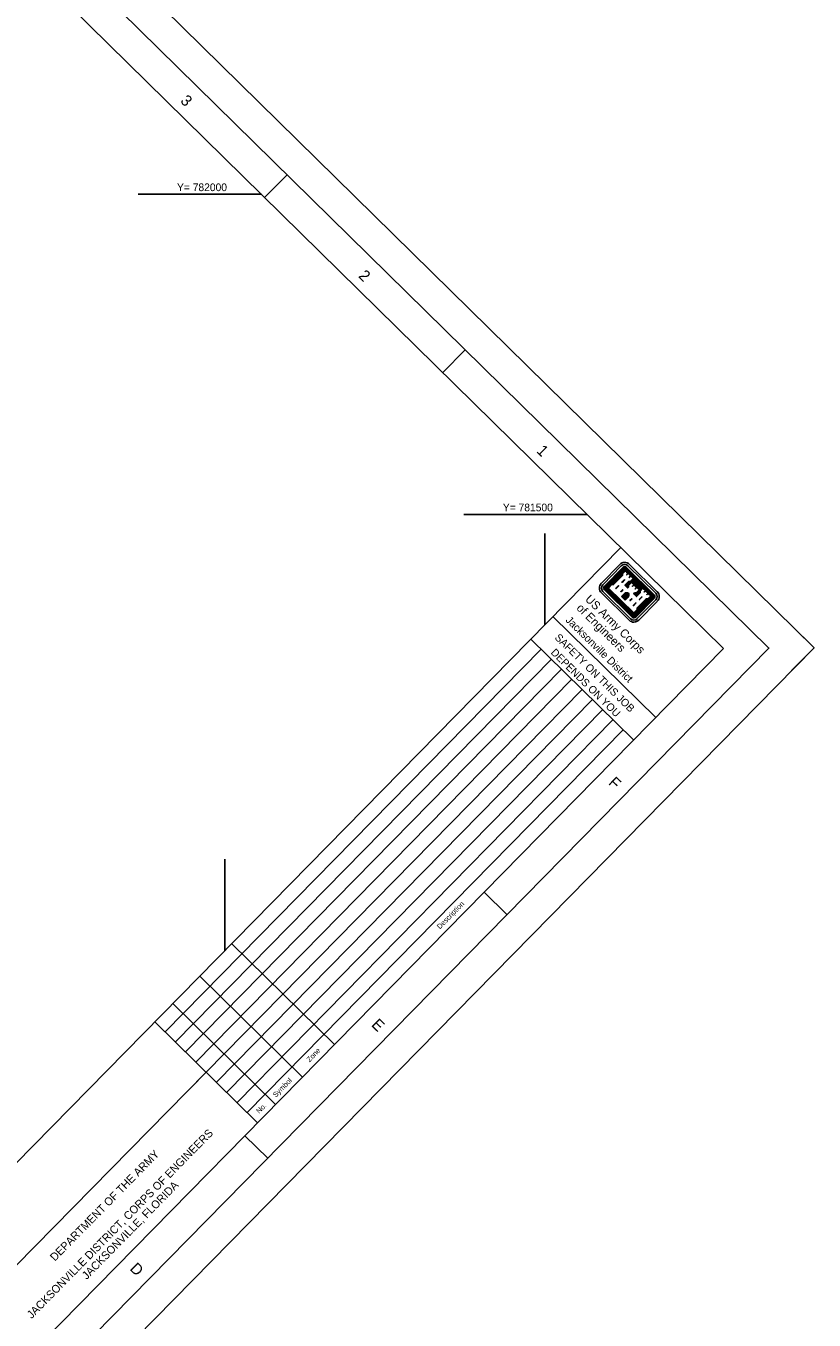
# Model space of a CAD drawing. Extents: x 614899 to 620420, y 778867 to 784376.
# Drawn here: x 619189 to 620420, y 780242 to 782263 of the extents above; entities that cross this region are included whole.
import ezdxf

# ---------------------------------------------------------------- set-up
doc = ezdxf.new("R2010")
doc.units = 0
for name, color, linetype in [('G-ANNO-NPLT', 7, 'Continuous'), ('G-ANNO-TEXT-LOGO', 7, 'Continuous'), ('G-ANNO-TEXT-TTLB', 7, 'Continuous'), ('G-ANNO-TTLB', 7, 'Continuous'), ('V-TOPO-COOR-STAT', 7, 'Continuous')]:
    doc.layers.add(name, color=color, linetype=linetype)

msp = doc.modelspace()

# ---------------------------------------------------------------- linework, layer by layer
at = {"layer": 'G-ANNO-NPLT'}
msp.add_lwpolyline([(617282, 784375.7), (620420.5, 781292), (618037.6, 778866.8), (614899.1, 781950.5)], close=True, dxfattribs=at)
msp.add_lwpolyline([(620385.4, 781256.3), (620420.5, 781292), (620384.8, 781327)], dxfattribs=at)
at = {"layer": 'G-ANNO-TEXT-LOGO'}
for p, q in [((620116.9, 781421.9), (620088.2, 781392.7)), ((620090.4, 781390.4), (620119.2, 781419.7)), ((620121.7, 781417.2), (620092.9, 781388)), ((620122.3, 781416.6), (620093.6, 781387.3)), ((620122.9, 781416), (620094.1, 781386.8)), ((620123.5, 781415.4), (620094.8, 781386.2)), ((620124.2, 781414.8), (620095.4, 781385.5)), ((620124.8, 781414.1), (620096.3, 781385.1)), ((620125.4, 781413.6), (620097.5, 781385.2)), ((620119.8, 781406.9), (620105.1, 781391.9)), ((620119.8, 781405.6), (620106.4, 781392)), ((620168.3, 781372.2), (620124.9, 781414.8)), ((620168.9, 781372.9), (620125.6, 781415.5)), ((620169.5, 781373.4), (620126.1, 781416.1)), ((620170.1, 781374.1), (620126.8, 781416.7)), ((620170.8, 781374.7), (620127.4, 781417.3)), ((620129.8, 781419.8), (620173.1, 781377.2)), ((620175.4, 781379.4), (620132, 781422)), ((620138.2, 781341.6), (620094.8, 781384.2)), ((620138.7, 781342.1), (620095.4, 781384.7)), ((620139.1, 781343.1), (620096.3, 781385.1)), ((620139.1, 781344.3), (620097.5, 781385.2)), ((620135.8, 781395.8), (620149.1, 781382.7)), ((620136.4, 781396.4), (620149.7, 781383.4)), ((620137, 781397), (620150.2, 781384)), ((620137.6, 781397.6), (620150.9, 781384.6)), ((620138.2, 781398.3), (620151.5, 781385.2)), ((620138.8, 781398.8), (620152.1, 781385.8)), ((620139.4, 781399.5), (620152.7, 781386.4)), ((620088.2, 781377.5), (620131.6, 781334.9)), ((620133.9, 781337.2), (620090.5, 781379.8)), ((620136.3, 781339.7), (620093, 781382.3)), ((620136.9, 781340.3), (620093.5, 781382.9)), ((620137.5, 781340.9), (620094.2, 781383.5)), ((620119.6, 781371.7), (620124.3, 781376.5)), ((620119.6, 781371.7), (620125.3, 781366.1)), ((620120.2, 781371.2), (620124.9, 781376)), ((620120.8, 781370.5), (620125.5, 781375.3)), ((620121.4, 781369.9), (620126.1, 781374.7)), ((620122, 781369.3), (620126.7, 781374.1)), ((620122.9, 781368.5), (620127.6, 781373.3)), ((620123.4, 781367.9), (620128.1, 781372.7)), ((620124.1, 781367.3), (620128.8, 781372.1)), ((620124.7, 781366.7), (620129.4, 781371.5)), ((620125.3, 781366.1), (620130, 781370.9)), ((620167, 781372.6), (620139.1, 781344.3)), ((620167.6, 781372.1), (620139.1, 781343.1)), ((620168.2, 781371.5), (620139.5, 781342.2)), ((620168.9, 781370.8), (620140.2, 781341.6)), ((620169.5, 781370.3), (620140.7, 781341)), ((620170.1, 781369.6), (620141.4, 781340.4)), ((620170.7, 781369), (620142, 781339.8)), ((620173.2, 781366.6), (620144.4, 781337.4)), ((620159.2, 781366.9), (620145.8, 781353.3)), ((620160.4, 781366.9), (620145.8, 781352)), ((620146.8, 781335.1), (620175.5, 781364.3))]:
    msp.add_line(p, q, dxfattribs=at)
for points in [[(620125.9, 781413.1), (620120.3, 781407.4), (620120.4, 781405), (620107, 781391.4), (620104.5, 781391.3), (620098.4, 781385.1), (620139.1, 781345.2), (620145.2, 781351.4), (620145.1, 781353.9), (620158.5, 781367.5), (620161, 781367.5), (620166.5, 781373.1), (620161.2, 781378.4), (620157, 781382.5), (620153.2, 781386.2), (620147.7, 781380.6), (620147.8, 781378.1), (620142.9, 781373.1), (620139.9, 781376), (620140.4, 781376.5), (620143, 781376.5), (620148.4, 781382.1), (620143.1, 781387.4), (620138.9, 781391.4), (620135.2, 781395.1), (620129.7, 781389.6), (620129.7, 781387), (620129.2, 781386.5), (620126.2, 781389.5), (620131.1, 781394.5), (620133.6, 781394.4), (620139.1, 781400), (620133.8, 781405.3), (620129.7, 781409.4), (620125.9, 781413.1)], [(620125.8, 781411.9), (620121.2, 781407.2), (620121.2, 781404.6), (620107.3, 781390.5), (620104.8, 781390.5), (620099.6, 781385.2), (620139.1, 781346.4), (620144.3, 781351.7), (620144.2, 781354.3), (620158.1, 781368.4), (620160.7, 781368.3), (620165.3, 781373.1), (620161.5, 781376.8), (620159.3, 781374.6), (620159, 781375), (620161.1, 781377.2), (620157.3, 781380.9), (620155.2, 781378.7), (620154.9, 781379), (620157.1, 781381.2), (620153.2, 781385), (620148.6, 781380.3), (620148.6, 781377.7), (620142.9, 781371.9), (620138.8, 781376), (620140.1, 781377.4), (620142.7, 781377.4), (620147.3, 781382.1), (620143.4, 781385.9), (620141.3, 781383.7), (620141, 781383.9), (620143.2, 781386.2), (620139.3, 781389.9), (620137.1, 781387.7), (620136.8, 781388.1), (620138.9, 781390.3), (620135.2, 781394), (620130.5, 781389.3), (620130.6, 781386.7), (620129.2, 781385.4), (620125.1, 781389.5), (620130.8, 781395.2), (620133.3, 781395.3), (620137.9, 781400), (620134.2, 781403.7), (620132, 781401.5), (620131.6, 781401.8), (620133.8, 781404), (620130, 781407.8), (620127.8, 781405.6), (620127.5, 781405.9), (620129.7, 781408.1), (620125.8, 781411.9)], [(620114.8, 781389), (620110.7, 781384.8), (620111.1, 781384.4), (620115.3, 781388.6), (620114.8, 781389)], [(620124.2, 781398.5), (620120.1, 781394.4), (620120.5, 781393.9), (620124.6, 781398.1), (620124.2, 781398.5)], [(620132.2, 781393.6), (620131.5, 781393.5), (620127.5, 781389.5), (620128.9, 781388.1), (620128.8, 781390), (620132.3, 781393.6)], [(620121.4, 781382.6), (620118.5, 781379.6), (620118.9, 781379.3), (620121.8, 781382.2), (620121.4, 781382.6)], [(620136.1, 781368.1), (620133.2, 781365.2), (620132.9, 781365.6), (620135.7, 781368.5), (620136.1, 781368.1)], [(620146.9, 781379.1), (620146.9, 781378.4), (620142.9, 781374.3), (620141.6, 781375.6), (620143.4, 781375.7), (620146.9, 781379.3)], [(620151.9, 781371.2), (620147.8, 781367.1), (620147.5, 781367.5), (620151.6, 781371.6), (620151.9, 781371.2)], [(620142.6, 781361.8), (620138.5, 781357.5), (620138.1, 781357.9), (620142.2, 781362.1), (620142.6, 781361.8)]]:
    msp.add_lwpolyline(points, dxfattribs=at)
for centre, major_axis, start_param, end_param in [((620124.6, 781414.4), (7.64, -7.51), 1.57078, 3.141576), ((620124.6, 781414.4), (5.34, -5.25), 1.57078, 3.141576), ((620124.6, 781414.4), (2.87, -2.82), 1.57078, 3.141576), ((620124.6, 781414.4), (2.25, -2.21), 1.57078, 3.141576), ((620124.6, 781414.4), (1.63, -1.6), 1.57078, 3.141576), ((620124.6, 781414.4), (1.01, -0.99), 1.57078, 3.141576), ((620124.6, 781414.4), (0.389, -0.382), 1.57078, 3.141576), ((620095.8, 781385.1), (-7.64, 7.51), 6.28317, 7.853966), ((620095.8, 781385.1), (-5.34, 5.25), 6.28317, 7.853966), ((620095.8, 781385.1), (-2.87, 2.82), 6.28317, 7.853966), ((620095.8, 781385.1), (-2.25, 2.21), 6.28317, 7.853966), ((620095.8, 781385.1), (-1.63, 1.6), 6.28317, 7.853966), ((620095.8, 781385.1), (-1.01, 0.99), 6.28317, 7.853966), ((620095.8, 781385.1), (-0.389, 0.382), 6.28317, 7.853966), ((620127.9, 781372.4), (-3.96, 3.89), 4.985832, 6.214359), ((620127.9, 781372.4), (-3.34, 3.28), 4.947465, 6.21436), ((620127.9, 781372.4), (-2.72, 2.68), 4.947465, 6.21436), ((620127.9, 781372.4), (-2.1, 2.07), 4.947465, 6.21436), ((620127.9, 781372.4), (-1.48, 1.46), 4.947465, 6.214359), ((620125.7, 781374.5), (1.48, -1.46), 0.068794, 1.335689), ((620125.7, 781374.5), (2.1, -2.07), 0.068794, 1.335689), ((620125.7, 781374.5), (2.72, -2.68), 0.068795, 1.335689), ((620125.7, 781374.5), (3.34, -3.28), 0.068795, 1.335689), ((620125.7, 781374.5), (3.96, -3.89), 0.068795, 1.29842), ((620167.9, 781371.9), (0.389, -0.382), 6.283169, 7.853965), ((620167.9, 781371.9), (1.01, -0.99), 6.283169, 7.853965), ((620167.9, 781371.9), (1.63, -1.6), 6.283169, 7.853965), ((620167.9, 781371.9), (2.25, -2.21), 6.283169, 7.853965), ((620167.9, 781371.9), (2.87, -2.82), 6.283169, 7.853965), ((620167.9, 781371.9), (5.34, -5.25), 6.28317, 7.853966), ((620167.9, 781371.9), (7.64, -7.51), 6.283169, 7.853965), ((620139.1, 781342.6), (7.64, -7.51), 4.712373, 6.28317), ((620139.1, 781342.6), (-5.34, 5.25), 1.570781, 3.141577), ((620139.1, 781342.6), (2.87, -2.82), 4.712373, 6.28317), ((620139.1, 781342.6), (2.25, -2.21), 4.712373, 6.28317), ((620139.1, 781342.6), (1.63, -1.6), 4.712373, 6.28317), ((620139.1, 781342.6), (1.01, -0.99), 4.712373, 6.28317), ((620139.1, 781342.6), (0.389, -0.382), 4.712373, 6.28317)]:
    msp.add_ellipse(centre, major_axis=major_axis, ratio=0.99964, start_param=start_param, end_param=end_param, dxfattribs=at)
at = {"layer": 'G-ANNO-TTLB'}
for p, q in [((619597.3, 782030.7), (619562.2, 781995.1)), ((619875.4, 781757.4), (619840.4, 781721.7)), ((620118.6, 781448.4), (617875.8, 779165.9)), ((620012.6, 781340.5), (620173.1, 781182.8)), ((619977.7, 781305.9), (620138.2, 781148.2)), ((619994.1, 781289.9), (619406.8, 780692.2)), ((620010.1, 781274.1), (619422.9, 780676.4)), ((620026.2, 781258.3), (619438.9, 780660.6)), ((620042.2, 781242.6), (619455, 780644.9)), ((620058.3, 781226.8), (619471, 780629.1)), ((620074.3, 781211), (619487.1, 780613.3)), ((620090.4, 781195.2), (619503.1, 780597.6)), ((620106.4, 781179.5), (619519.2, 780581.8)), ((620122.5, 781163.7), (619535.2, 780566)), ((619940.8, 780875.1), (619905.2, 780910.2)), ((619510.8, 780829.8), (619671.3, 780672.1)), ((619460.9, 780779), (619621.4, 780621.4)), ((619418.8, 780736.2), (619579.3, 780578.5)), ((619390.9, 780707.8), (619551.4, 780550.1)), ((618868.2, 780016.3), (619471.1, 780629)), ((619471.1, 780629), (619446.3, 780603.7)), ((619567.1, 780494.7), (619531.4, 780529.8))]:
    msp.add_line(p, q, dxfattribs=at)
for points in [[(614969.8, 781951.2), (618036.9, 778937.5), (620349.8, 781291.3), (617282.6, 784305)], [(620279.1, 781290.7), (617336.7, 784181.8), (615094, 781899.2), (618036.3, 779008.2)]]:
    msp.add_lwpolyline(points, close=True, dxfattribs=at)
at = {"layer": 'V-TOPO-COOR-STAT'}
for p, q in [((619364.6, 782000), (619557.2, 782000)), ((619873.5, 781500), (620066.1, 781500)), ((620000, 781327.8), (620000, 781470.4)), ((619500, 780818.9), (619500, 780961.6))]:
    msp.add_line(p, q, dxfattribs=at)

# ---------------------------------------------------------------- texts
at = {"layer": 'G-ANNO-TEXT-TTLB'}
for s, height, rotation, p in [('US Army Corps', 13.086, 315.5037, (620062, 781366.6)), ('of Engineers', 13.086, 315.5037, (620048.4, 781352.8)), ('Jacksonville District', 11.9, 315.5037, (620031.4, 781334)), ('SAFETY ON THIS JOB', 11.9, 315.5037, (620014.5, 781306.7)), ('DEPENDS ON YOU', 11.9, 315.5037, (620008.2, 781283.5)), ('Description', 8, 45.5037, (619836.1, 780851.8)), ('Zone', 8, 45.5037, (619632.6, 780644.3)), ('Symbol', 8, 45.5037, (619579.9, 780589)), ('No.', 8, 45.5037, (619553.9, 780563.9)), ('JACKSONVILLE DISTRICT, CORPS OF ENGINEERS', 12.5, 45.5037, (619198.5, 780243.3)), ('DEPARTMENT OF THE ARMY', 12.5, 45.5037, (619234.8, 780333)), ('JACKSONVILLE, FLORIDA', 12.5, 45.5037, (619284.5, 780304.4))]:
    msp.add_text(s, height=height, rotation=rotation, dxfattribs=at).set_placement(p)
at = {"layer": 'G-ANNO-TTLB'}
for s, p in [('3', (619429.6, 782144.8)), ('2', (619707.8, 781871.5)), ('1', (619985.9, 781598.2)), ('F', (620098.1, 781079.7)), ('E', (619728, 780702)), ('D', (619350.7, 780321.1))]:
    msp.add_text(s, height=17.5, rotation=315.5037, dxfattribs=at).set_placement(p)
at = {"layer": 'V-TOPO-COOR-STAT'}
for s, p in [('Y= 782000', (619425.5, 782005)), ('Y= 781500', (619934.4, 781505))]:
    msp.add_text(s, height=12, dxfattribs=at).set_placement(p)

doc.saveas('drawing.dxf')
